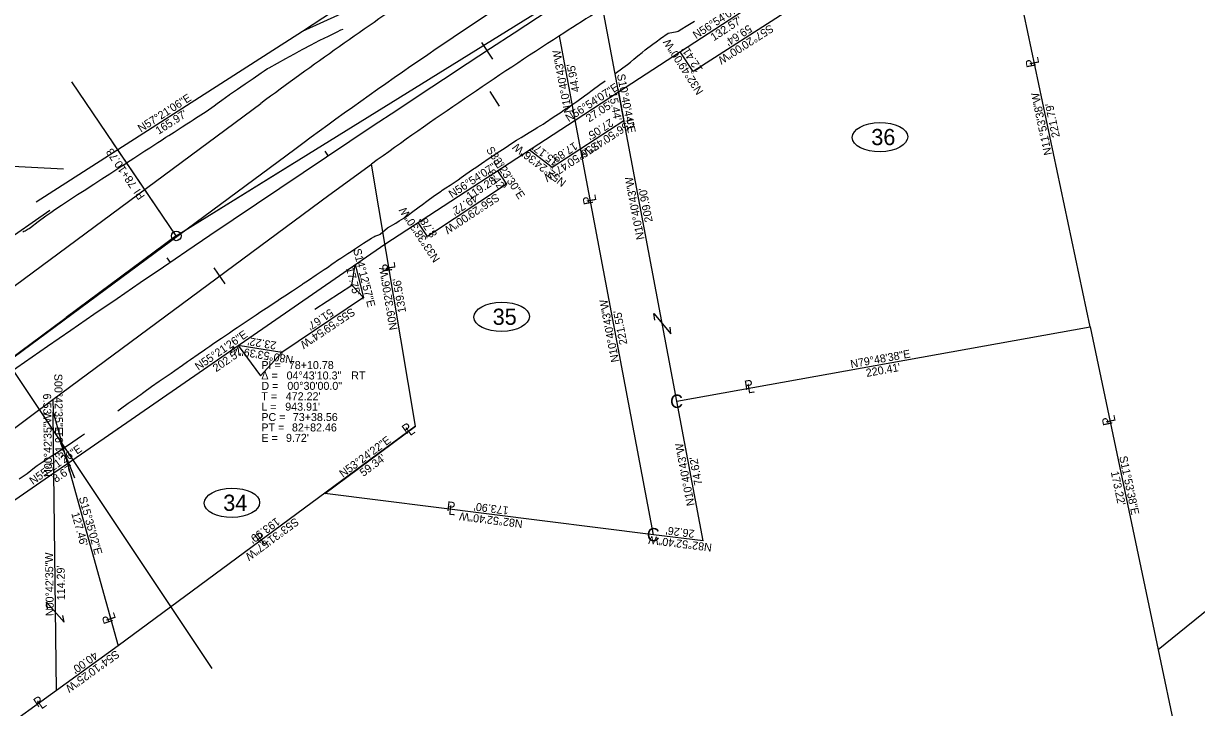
# Model space of a CAD drawing. Extents: x 1145508 to 2262867, y -3126236 to 2021677.
# Drawn here: x 1150426 to 1151042, y 2019521 to 2019881 of the extents above; entities that cross this region are included whole.
import ezdxf

# ---------------------------------------------------------------- set-up
doc = ezdxf.new("R2010")
doc.units = 0
for name, color, linetype in [('Default', 7, 'Continuous'), ('DSN_RDWY_Alignment', 7, 'Continuous'), ('DSN_RDWY_Alignment Annotation', 7, 'Continuous'), ('DSN_RDWY_Const Limits', 7, 'Continuous'), ('DSN_ROW_Annotation', 7, 'Continuous'), ('DSN_ROW_Esmnt', 7, 'Continuous'), ('DSN_ROW_Line', 7, 'Continuous'), ('DSN_ROW_Line-Annotation', 7, 'Continuous'), ('DSN_ROW_Prop-Line', 7, 'Continuous'), ('DSN_ROW_Prop-Line-Annotation', 7, 'Continuous'), ('E_Const Align', 7, 'Continuous'), ('EX_PRIMARY_CTL', 7, 'Continuous'), ('EX_PROPERTY', 7, 'Continuous'), ('EX_ROW', 7, 'Continuous'), ('EX_SIGN', 7, 'Continuous'), ('SHET_Annotations', 7, 'Continuous')]:
    doc.layers.add(name, color=color, linetype=linetype)

msp = doc.modelspace()

# ---------------------------------------------------------------- linework, layer by layer
at = {"layer": 'Default'}
msp.add_line((1150568.87, 2019814.51), (1149723.97, 2019188.76), dxfattribs=at)
msp.add_arc((1151932.9, 2017972.79), 2291.83, 122.23857, 126.5246, dxfattribs=at)
at = {"layer": 'DSN_RDWY_Alignment'}
for p, q in [((1150506.7, 2019769.08), (1150907.91, 2020018.13)), ((1150127.35, 2019487.87), (1150506.7, 2019769.08)), ((1150421.06, 2019698.5), (1150525.38, 2019541.87))]:
    msp.add_line(p, q, dxfattribs=at)
for points in [[(1150506.7, 2019769.08), (1150451.8, 2019849.9)], [(1150370.24, 2019808.25), (1150447.48, 2019804.37)], [(1150387.95, 2019746.24), (1150440.34, 2019782.58)]]:
    msp.add_lwpolyline(points, dxfattribs=at)
msp.add_circle((1150506.7, 2019769.08), 2.5, dxfattribs=at)
at = {"layer": 'DSN_RDWY_Alignment Annotation'}
for p, q in [((1150666.86, 2019870.68), (1150672.68, 2019861.8)), ((1150506.7, 2019769.08), (1150472.99, 2019818.71)), ((1150472.99, 2019818.71), (1150472.99, 2019818.71)), ((1150584.72, 2019813.53), (1150586.39, 2019811.03)), ((1150506.7, 2019769.08), (1150567.88, 2019807.05)), ((1150506.7, 2019769.08), (1150448.86, 2019726.2)), ((1150501.79, 2019757.61), (1150503.48, 2019755.13))]:
    msp.add_line(p, q, dxfattribs=at)
at = {"layer": 'DSN_RDWY_Const Limits'}
for points in [[(1150737.08, 2019854.38), (1150741.09, 2019857.35), (1150743.5, 2019859.13), (1150745.05, 2019860.39), (1150746.82, 2019861.86), (1150748.93, 2019863.57), (1150751.22, 2019865.42), (1150752.82, 2019866.72), (1150756.78, 2019869.77), (1150758.61, 2019871.07), (1150760.85, 2019872.65), (1150764.86, 2019875.62), (1150769.6, 2019876.33), (1150770.12, 2019876.65), (1150772.02, 2019877.81), (1150774.37, 2019879.25), (1150778.67, 2019881.77)], [(1150429.46, 2019772.95), (1150429.46, 2019772.95), (1150430.18, 2019773.51), (1150434.17, 2019776.58), (1150438.17, 2019779.62), (1150440.76, 2019781.44), (1150442.31, 2019782.48), (1150444.49, 2019783.92), (1150446.51, 2019785.24), (1150450.71, 2019787.99), (1150453.34, 2019789.7), (1150454.92, 2019790.74), (1150459.14, 2019793.48), (1150462.55, 2019795.71), (1150463.34, 2019796.23), (1150465.49, 2019797.64), (1150467.55, 2019798.98), (1150471.76, 2019801.72), (1150475.98, 2019804.45), (1150478.11, 2019805.82), (1150480.2, 2019807.18), (1150480.63, 2019807.46), (1150484.41, 2019809.92), (1150488.62, 2019812.66), (1150490.21, 2019813.69), (1150492.84, 2019815.39), (1150497.06, 2019818.12), (1150498.72, 2019819.19), (1150501.29, 2019820.85), (1150502.82, 2019821.84), (1150505.51, 2019823.57), (1150509.73, 2019826.29), (1150512.27, 2019827.92), (1150513.96, 2019829.01), (1150515.06, 2019829.71), (1150515.47, 2019829.97), (1150516.86, 2019830.86), (1150518.2, 2019831.71), (1150522.4, 2019834.47), (1150526.55, 2019837.3), (1150528.2, 2019838.58), (1150530.54, 2019840.37), (1150534.53, 2019843.21), (1150534.64, 2019843.28), (1150538.8, 2019846.1), (1150540.5, 2019847.28), (1150542.93, 2019848.96), (1150547.06, 2019851.82), (1150551.2, 2019854.67), (1150552.3, 2019855.4), (1150552.89, 2019855.79), (1150554.62, 2019856.94), (1150555.43, 2019857.37), (1150559.85, 2019859.8), (1150564.25, 2019862.26), (1150566.09, 2019863.28), (1150568.66, 2019864.71), (1150571.11, 2019866.05), (1150573.1, 2019867.1), (1150577.56, 2019869.47), (1150579.41, 2019870.47), (1150582.02, 2019871.83), (1150586.58, 2019874.04), (1150590.44, 2019875.91), (1150591.15, 2019876.25), (1150593.14, 2019877.21), (1150594.24, 2019877.58)], [(1150476.02, 2019677.32), (1150477.45, 2019678.33), (1150481.51, 2019681.22), (1150485.57, 2019684.1), (1150486.5, 2019684.77), (1150488.07, 2019685.88), (1150488.88, 2019686.46), (1150488.89, 2019686.47), (1150488.89, 2019686.47), (1150489.62, 2019687), (1150493.64, 2019689.93), (1150497.72, 2019692.79), (1150500.3, 2019694.57), (1150501.82, 2019695.62), (1150503.95, 2019697.1), (1150505.91, 2019698.46), (1150510.01, 2019701.28), (1150512.56, 2019703.06), (1150514.1, 2019704.12), (1150518.19, 2019706.96), (1150521.51, 2019709.27), (1150522.28, 2019709.8), (1150524.37, 2019711.26), (1150526.35, 2019712.68), (1150530.46, 2019715.47), (1150534.58, 2019718.27), (1150536.66, 2019719.68), (1150538.7, 2019721.07), (1150539.12, 2019721.36), (1150542.84, 2019723.85), (1150546.99, 2019726.59), (1150548.56, 2019727.62), (1150551.15, 2019729.33), (1150555.3, 2019732.08), (1150556.93, 2019733.16), (1150559.45, 2019734.83), (1150560.95, 2019735.83), (1150563.6, 2019737.58), (1150567.75, 2019740.33), (1150570.24, 2019741.99), (1150571.9, 2019743.09), (1150572.97, 2019743.8), (1150573.37, 2019744.07), (1150574.73, 2019744.97), (1150576.04, 2019745.84), (1150580.19, 2019748.6), (1150584.32, 2019751.38), (1150586.02, 2019752.55), (1150588.42, 2019754.21), (1150592.41, 2019756.96), (1150592.52, 2019757.03), (1150596.67, 2019759.79), (1150598.41, 2019760.88), (1150600.82, 2019762.54), (1150604.93, 2019765.35), (1150609.2, 2019767.91), (1150610.34, 2019768.57), (1150610.97, 2019768.89), (1150612.94, 2019769.65), (1150613.75, 2019770.08), (1150617.61, 2019773.26), (1150621.94, 2019775.73), (1150623.64, 2019776.92), (1150626.1, 2019778.47), (1150628.42, 2019779.97), (1150630.2, 2019781.3), (1150634.19, 2019784.28), (1150635.85, 2019785.54), (1150638.14, 2019787.34), (1150642.19, 2019790.24), (1150645.68, 2019792.59), (1150646.32, 2019793.02), (1150648.13, 2019794.24), (1150650.45, 2019795.81), (1150654.57, 2019798.59), (1150656.21, 2019799.73), (1150658.67, 2019801.43), (1150660.44, 2019802.65), (1150662.76, 2019804.26), (1150663.32, 2019804.65), (1150666.86, 2019807.1), (1150670.98, 2019809.89), (1150672.77, 2019811.09), (1150675.12, 2019812.65), (1150679.27, 2019815.41), (1150681.03, 2019816.59), (1150683.41, 2019818.18), (1150685.26, 2019819.37), (1150687.62, 2019820.83), (1150691.89, 2019823.4), (1150695.38, 2019825.5), (1150696.16, 2019825.97), (1150698.02, 2019827.09), (1150699.22, 2019827.81), (1150700.4, 2019828.59), (1150704.54, 2019831.35), (1150708.67, 2019834.13), (1150710.51, 2019835.38), (1150712.8, 2019836.92), (1150716.94, 2019839.69), (1150716.97, 2019839.7), (1150720.96, 2019842.63), (1150722.72, 2019843.94), (1150724.97, 2019845.6), (1150728.94, 2019848.62), (1150731.77, 2019850.57)], [(1150429.47, 2019772.96), (1150429.24, 2019772.8), (1150428.94, 2019772.6), (1150428.4, 2019772.26), (1150427.86, 2019771.95), (1150427.3, 2019771.65), (1150426.74, 2019771.37), (1150426.73, 2019771.37), (1150426.16, 2019771.11)], [(1150450.17, 2019659.47), (1150456.97, 2019664.19), (1150458.49, 2019665.24)], [(1150424.16, 2019641.6), (1150426.88, 2019643.3), (1150428.34, 2019644.31), (1150432.25, 2019647.4), (1150433.67, 2019648.5), (1150436.35, 2019650.23), (1150439.73, 2019652.55), (1150440.46, 2019653.04), (1150444.68, 2019655.7), (1150448.79, 2019658.51), (1150450.17, 2019659.47)]]:
    msp.add_lwpolyline(points, dxfattribs=at)
at = {"layer": 'DSN_ROW_Esmnt'}
for p, q in [((1150572.87, 2019876.53), (1150612.27, 2019902.61)), ((1150828.11, 2019887.59), (1150777.9, 2019855.4)), ((1150777.9, 2019855.4), (1150771.18, 2019865.82)), ((1150738.76, 2019844.7), (1150741.63, 2019829.52)), ((1150741.63, 2019829.52), (1150718.97, 2019814.72)), ((1150704, 2019804.94), (1150691.98, 2019814.2)), ((1150718.97, 2019814.72), (1150704, 2019804.94)), ((1150675.3, 2019803.33), (1150679.94, 2019796.3)), ((1150679.94, 2019796.3), (1150638.49, 2019768.85)), ((1150638.49, 2019768.85), (1150633.62, 2019776.16)), ((1150600.55, 2019753.99), (1150604.91, 2019736.79)), ((1150604.91, 2019736.79), (1150562.07, 2019707.89)), ((1150562.07, 2019707.89), (1150539.15, 2019711.56))]:
    msp.add_line(p, q, dxfattribs=at)
at = {"layer": 'DSN_ROW_Line'}
for p, q in [((1150738.77, 2019844.7), (1150849.82, 2019917.09)), ((1150572.87, 2019876.53), (1150631.65, 2019903.38)), ((1150433.12, 2019786.99), (1150572.87, 2019876.53)), ((1150716.11, 2019829.93), (1150738.77, 2019844.7)), ((1150616.18, 2019764.79), (1150716.11, 2019829.93)), ((1150449.52, 2019649.64), (1150616.18, 2019764.79)), ((1150442.39, 2019644.71), (1150449.52, 2019649.64)), ((1150360.74, 2019588.29), (1150442.39, 2019644.71))]:
    msp.add_line(p, q, dxfattribs=at)
at = {"layer": 'DSN_ROW_Line-Annotation'}
for centre in [(1150876.04, 2019820.95), (1150677.47, 2019726.6), (1150535.91, 2019628.93)]:
    msp.add_ellipse(centre, major_axis=(14.54, 0.23), ratio=0.529773, dxfattribs=at)
at = {"layer": 'DSN_ROW_Prop-Line'}
for p, q in [((1150986.32, 2019721.27), (1150940.61, 2019938.3)), ((1150769.39, 2019682.28), (1150730.49, 2019888.55)), ((1150716.11, 2019829.93), (1150707.78, 2019874.1)), ((1150757.16, 2019612.21), (1150716.11, 2019829.93)), ((1150632.25, 2019669.15), (1150609.13, 2019806.78)), ((1150769.39, 2019682.28), (1150986.32, 2019721.27)), ((1150986.32, 2019721.27), (1151022.02, 2019551.77)), ((1150441.92, 2019683.15), (1150442, 2019676.62)), ((1150783.22, 2019608.95), (1150769.39, 2019682.28)), ((1150442, 2019676.62), (1150476.24, 2019553.85)), ((1150442.39, 2019644.71), (1150442, 2019676.62)), ((1150632.25, 2019669.15), (1150476.24, 2019553.85)), ((1150584.6, 2019633.77), (1150632.25, 2019669.15)), ((1150443.81, 2019530.43), (1150442.39, 2019644.71)), ((1150757.16, 2019612.21), (1150584.6, 2019633.77)), ((1150783.22, 2019608.95), (1150757.16, 2019612.21)), ((1150476.24, 2019553.85), (1150443.81, 2019530.43)), ((1150443.81, 2019530.43), (1150356.61, 2019467.49))]:
    msp.add_line(p, q, dxfattribs=at)
at = {"layer": 'DSN_ROW_Prop-Line-Annotation'}
for p, q in [((1150757.9, 2019724.86), (1150757.42, 2019728.37)), ((1150757.42, 2019728.37), (1150766.32, 2019717.61)), ((1150766.32, 2019717.61), (1150765.85, 2019721.12)), ((1150439.13, 2019573.29), (1150438.56, 2019576.79)), ((1150438.56, 2019576.79), (1150447.77, 2019566.3)), ((1150447.77, 2019566.3), (1150447.2, 2019569.8))]:
    msp.add_line(p, q, dxfattribs=at)
at = {"layer": 'E_Const Align'}
msp.add_arc((1156951.39, 2010282.18), 11459.16, 121.829445, 126.548983, dxfattribs=at)
msp.add_arc((1156951.39, 2010282.18), 11459.16, 121.829445, 126.548983, dxfattribs=at)
at = {"layer": 'EX_PROPERTY'}
for p, q in [((1151276.43, 2019758.58), (1151022.1, 2019551.74)), ((1151022.1, 2019551.74), (1151167.21, 2018862.77))]:
    msp.add_line(p, q, dxfattribs=at)
at = {"layer": 'EX_ROW'}
for p, q in [((1150364.58, 2019700.53), (1150551.02, 2019838.62)), ((1150586.73, 2019790.4), (1150609.13, 2019806.78)), ((1150441.92, 2019683.15), (1150586.73, 2019790.4)), ((1150361.96, 2019623.93), (1150441.92, 2019683.15))]:
    msp.add_line(p, q, dxfattribs=at)
for radius, start, end in [(2321.83, 124.0135, 126.5246), (2261.83, 122.23857, 122.79592), (2261.83, 122.79592, 125.82162)]:
    msp.add_arc((1151932.9, 2017972.79), radius, start, end, dxfattribs=at)
at = {"layer": 'EX_SIGN'}
for p, q in [((1150671.22, 2019844.85), (1150676.19, 2019837.24)), ((1150526.38, 2019752.3), (1150532.09, 2019743.9)), ((1150445.83, 2019660.8), (1150453.35, 2019642.01))]:
    msp.add_line(p, q, dxfattribs=at)
at = {"layer": 'SHET_Annotations'}
msp.add_line((1150598.8, 2019743.14), (1150604.91, 2019736.79), dxfattribs=at)
for points in [[(1150579.33, 2019730.6), (1150598.8, 2019743.14), (1150600.55, 2019753.99)], [(1150539.15, 2019711.56), (1150550.83, 2019695.69), (1150562.07, 2019707.89)]]:
    msp.add_lwpolyline(points, dxfattribs=at)

# ---------------------------------------------------------------- texts
at = {"layer": 'DSN_RDWY_Alignment Annotation'}
for s, p in [('78+10.78', (1150486.22, 2019796.03)), ('PI ', (1150490.38, 2019789.9))]:
    msp.add_text(s, height=4.2, rotation=124.18921, dxfattribs=at).set_placement(p)
for s, p in [('PI = ', (1150551.35, 2019699.17)), ('78+10.78', (1150565.75, 2019699.17)), ('Δ = ', (1150551.35, 2019693.71)), ('04°43\'10.3"', (1150564.58, 2019693.71)), (' RT', (1150596.94, 2019693.71)), ('D = ', (1150551.35, 2019688.25)), ('00°30\'00.0"', (1150564.98, 2019688.25)), ('T = ', (1150551.35, 2019682.79)), ("472.22'", (1150564.16, 2019682.79)), ('L = ', (1150551.35, 2019677.33)), ("943.91'", (1150563.87, 2019677.33)), ('PC = ', (1150551.35, 2019671.87)), ('73+38.56', (1150567.85, 2019671.87)), ('PT = ', (1150551.35, 2019666.41)), ('82+82.46', (1150567.39, 2019666.41)), ('E = ', (1150551.35, 2019660.95)), ("9.72'", (1150564.26, 2019660.95))]:
    msp.add_text(s, height=4.2, dxfattribs=at).set_placement(p)
at = {"layer": 'DSN_ROW_Annotation'}
for s, rotation, p in [('N56°54\'07"E', 33.09799, (1150779.52, 2019872.33)), ("132.57'", 33.09799, (1150788.82, 2019871.24)), ('S57°20\'00"W', 212.66677, (1150818.45, 2019880.33)), ("59.64'", 212.66677, (1150807.12, 2019880.19)), ('N32°49\'00"W', 122.81677, (1150783.57, 2019844.94)), ('N10°40\'43"W', 100.67875, (1150714.41, 2019834.09)), ("12.41'", 122.81677, (1150783.24, 2019856.52)), ("44.95'", 100.67875, (1150718.47, 2019844.95)), ('S10°40\'44"E', 280.67875, (1150737.97, 2019853.75)), ('N56°54\'07"E', 33.09795, (1150712.66, 2019828.75)), ('N57°21\'06"E', 32.64829, (1150488.15, 2019823.31)), ("27.05'", 33.09795, (1150723.39, 2019828.59)), ("15.44'", 280.67875, (1150733.67, 2019844.18)), ('N11°53\'38"W', 101.89383, (1150966.31, 2019811.92)), ("165.97'", 32.64829, (1150497.45, 2019822.15)), ("221.79'", 101.89383, (1150970.49, 2019821.19)), ('S56°50\'47"W', 213.15373, (1150745.67, 2019831.09)), ("27.05'", 213.15373, (1150734.34, 2019830.85)), ('S33°23\'30"E', 303.39177, (1150669.15, 2019814.31)), ('N52°24\'36"W', 142.4101, (1150711.75, 2019797.84)), ("15.17'", 142.4101, (1150707.56, 2019808.64)), ('S56°50\'47"W', 213.15373, (1150726.86, 2019818.8)), ("17.89'", 213.15373, (1150715.52, 2019818.56)), ('N56°54\'07"E', 33.09795, (1150651.37, 2019788.8)), ("8.42'", 303.39177, (1150669.82, 2019802.39)), ("119.28'", 33.09795, (1150660.67, 2019787.7)), ('N10°40\'43"W', 100.67875, (1150752.41, 2019767.5)), ('S56°29\'00"W', 213.51677, (1150674.52, 2019791.63)), ("49.72'", 213.51677, (1150663.19, 2019791.33)), ("209.90'", 100.67875, (1150756.78, 2019776.68)), ('N33°38\'30"W', 123.64177, (1150645.31, 2019756.97)), ("8.78'", 123.64177, (1150643.87, 2019769.96)), ('S14°12\'57"E', 284.21588, (1150599.49, 2019761.86)), ("17.75'", 284.21588, (1150595.79, 2019752.04)), ('N09°32\'06"W', 99.53508, (1150622.79, 2019720)), ("139.56'", 99.53508, (1150627.35, 2019729.09)), ('N10°40\'43"W', 100.67875, (1150739.1, 2019703.15)), ('S55°59\'54"W', 214.00177, (1150598.73, 2019731.53)), ("51.67'", 214.00177, (1150587.4, 2019731.12)), ("221.55'", 100.67875, (1150743.47, 2019712.33)), ('N55°21\'26"E', 34.64281, (1150518.31, 2019698.26)), ("23.22'", 170.89421, (1150559.47, 2019713.47)), ("202.57'", 34.64281, (1150527.64, 2019697.42)), ('N80°53\'39"W', 170.89421, (1150568.3, 2019705.98)), ('N79°48\'38"E', 10.18954, (1150860.91, 2019699.65)), ("220.41'", 10.18954, (1150869.06, 2019695.02)), ('S00°42\'35"E', 270.70962, (1150442.65, 2019696.66)), ("6.53'", 270.70962, (1150436.78, 2019686.27)), ('N00°42\'35"W', 90.70962, (1150441.52, 2019642.59)), ("31.91'", 90.70962, (1150447.39, 2019652.58)), ('N53°24\'22"E', 36.5939, (1150594.19, 2019642.02)), ('N55°21\'26"E', 34.64281, (1150431.41, 2019638.22)), ("59.34'", 36.5939, (1150604.92, 2019642.51)), ('N10°40\'43"W', 100.67875, (1150778.77, 2019627.7)), ("8.67'", 34.64281, (1150443.55, 2019639.31)), ("74.62'", 100.67875, (1150782.83, 2019638.55)), ('S11°53\'38"E', 281.89383, (1151001.6, 2019653.11)), ("173.22'", 281.89383, (1150997.15, 2019645.12)), ('S15°35\'02"E', 285.58395, (1150455.48, 2019631.62)), ("127.46'", 285.58395, (1150451.56, 2019623.36)), ('N82°52\'40"W', 172.8777, (1150688.69, 2019619.86)), ("173.90'", 172.8777, (1150681.3, 2019626.83)), ('S53°31\'57"W', 216.46748, (1150569.07, 2019621.34)), ("193.99'", 216.46748, (1150559.14, 2019621.46)), ('N82°52\'40"W', 172.8777, (1150788, 2019607.45)), ("26.26'", 172.8777, (1150778.91, 2019614.63)), ('N00°42\'35"W', 90.70962, (1150442.42, 2019569.5)), ("114.29'", 90.70962, (1150448.32, 2019577.78)), ('S54°10\'25"W', 215.82629, (1150474.96, 2019551.81)), ("40.00'", 215.82629, (1150463.65, 2019551.05))]:
    msp.add_text(s, height=4.2, rotation=rotation, dxfattribs=at).set_placement(p)
at = {"layer": 'DSN_ROW_Esmnt'}
for p in [(1150776.9, 2019854.4), (1150703, 2019803.94), (1150678.94, 2019795.3), (1150637.49, 2019767.85), (1150603.91, 2019735.79), (1150561.07, 2019706.89)]:
    msp.add_text('b', height=2, dxfattribs=at).set_placement(p)
at = {"layer": 'DSN_ROW_Line-Annotation'}
for s, p in [('36', (1150871.47, 2019816.75)), ('35', (1150672.74, 2019722.39)), ('34', (1150531.34, 2019624.72))]:
    msp.add_text(s, height=8.5, dxfattribs=at).set_placement(p)
at = {"layer": 'DSN_ROW_Prop-Line-Annotation'}
for s, rotation, p in [('P', 101.65075, (1150958.04, 2019858.08)), ('L', 101.65075, (1150959.68, 2019859.61)), ('P', 100.12074, (1150725.57, 2019785.95)), ('L', 100.12074, (1150727.25, 2019787.43)), ('P', 98.4852, (1150620.11, 2019750.57)), ('L', 98.4852, (1150621.83, 2019752)), ('P', 9.15391, (1150805.31, 2019688.04)), ('L', 9.15391, (1150806.77, 2019686.34)), ('P', 101.65075, (1150998.16, 2019670.08)), ('L', 101.65075, (1150999.8, 2019671.61)), ('P', 35.83164, (1150627.39, 2019664.74)), ('L', 35.83164, (1150629.45, 2019663.86)), ('P', 353.41786, (1150648.42, 2019624.81)), ('L', 353.41786, (1150649.36, 2019622.77)), ('P', 35.83164, (1150550.23, 2019607.46)), ('L', 35.83164, (1150552.3, 2019606.59)), ('P', 108.44113, (1150473.61, 2019566.39)), ('L', 108.44113, (1150475.06, 2019568.11)), ('P', 34.3871, (1150433.9, 2019521.31)), ('L', 34.3871, (1150435.94, 2019520.38))]:
    msp.add_text(s, height=5, rotation=rotation, dxfattribs=at).set_placement(p)
at = {"layer": 'EX_PRIMARY_CTL'}
for p in [(1150765.89, 2019678.78), (1150753.66, 2019608.71)]:
    msp.add_text('C', height=7, dxfattribs=at).set_placement(p)

doc.saveas('drawing.dxf')
